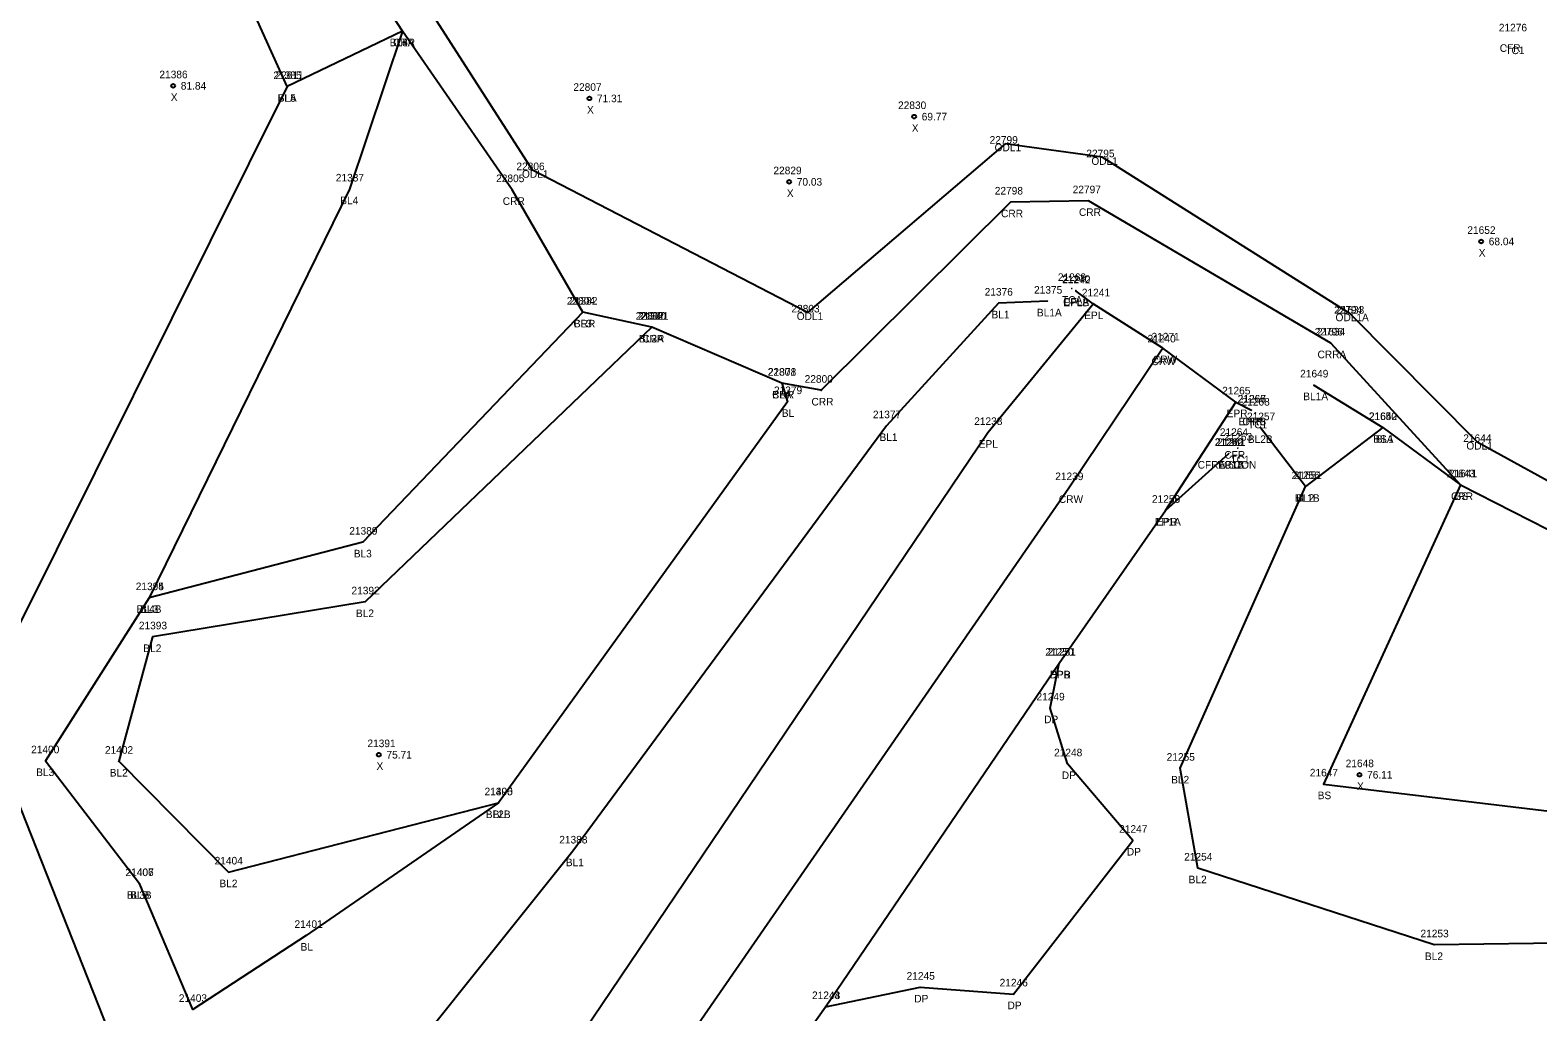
# Model space of a CAD drawing. Extents: x 2266664 to 2272385, y 716533 to 724777.
# Drawn here: x 2269825.5 to 2270024.3, y 721208.7 to 721338.1 of the extents above; entities that cross this region are included whole.
import ezdxf

# ---------------------------------------------------------------- set-up
doc = ezdxf.new("R2010")
doc.units = 0
for name, color, linetype in [('RD_DTM_BkLn1', 7, 'Continuous'), ('RD_DTM_BkLn2', 7, 'Continuous'), ('RD_EX_Conc_txCode', 7, 'Continuous'), ('RD_EX_Driveway', 7, 'Continuous'), ('RD_EX_Driveway_txCode', 7, 'Continuous'), ('RD_EX_H2O', 7, 'Continuous'), ('RD_EX_H2O_txCode', 7, 'Continuous'), ('RD_EX_Road', 7, 'Continuous'), ('RD_EX_Road_txCode', 7, 'Continuous'), ('RD_Sketch8', 7, 'Continuous'), ('RD_SMD_Locator', 7, 'Continuous'), ('RD_SMD_Misc', 7, 'Continuous')]:
    doc.layers.add(name, color=color, linetype=linetype)

msp = doc.modelspace()

# ---------------------------------------------------------------- linework, layer by layer
at = {"layer": 'RD_DTM_BkLn1'}
for points in [[(2269859.38, 721330.7), (2269841.69, 721369.98), (2269832.71, 721368.75)], [(2269874.61, 721338.02), (2269859.38, 721330.7), (2269818.8, 721249.22), (2269835.85, 721206.17)], [(2269874.61, 721338.02), (2269867.6, 721317.19), (2269841.23, 721263.3)], [(2269959.65, 721302.4), (2269953.17, 721302.14), (2269938.41, 721285.97), (2269897.06, 721229.9), (2269866, 721191.05), (2269835.85, 721206.17)], [(2269984.48, 721289.11), (2269974.85, 721296.23), (2269965.67, 721302.04)], [(2269907.47, 721298.96), (2269898.39, 721300.95), (2269869.39, 721270.62), (2269841.23, 721263.3), (2269827.53, 721241.79), (2269839.94, 721225.6)], [(2269907.47, 721298.96), (2269869.68, 721262.75), (2269841.64, 721258.14), (2269837.21, 721241.73), (2269851.67, 721227.13), (2269887.25, 721236.25)], [(2269213.98, 720188.15), (2269268.31, 720269.94), (2269268.47, 720270.09), (2269327.62, 720355.72), (2269383.6, 720437.51), (2269437.73, 720515.95), (2269495.99, 720600.52), (2269554.62, 720685.64), (2269615.22, 720774.38), (2269673.5, 720859.19), (2269731.5, 720942.79), (2269790.07, 721028.11), (2269844, 721106.36), (2269904.2, 721193.5), (2269962.45, 721277.81), (2269974.66, 721295.97), (2269974.85, 721296.23)], [(2269924.59, 721291.58), (2269925.37, 721289.15), (2269887.25, 721236.25), (2269861.92, 721218.77), (2269846.95, 721209.01), (2269839.94, 721225.6)], [(2269994.76, 721291.35), (2270003.84, 721285.73), (2269993.63, 721277.95)], [(2270089.16, 721218.61), (2270010.6, 721217.53), (2269979.45, 721227.65), (2269977.14, 721240.81), (2269993.63, 721277.95), (2269987.72, 721285.71)]]:
    msp.add_lwpolyline(points, dxfattribs=at)
at = {"layer": 'RD_DTM_BkLn2'}
msp.add_lwpolyline([(2270003.84, 721285.73), (2270014.08, 721278.19), (2269996.03, 721238.74), (2270067.72, 721230.16), (2270074.38, 721232.34)], dxfattribs=at)
at = {"layer": 'RD_EX_Driveway'}
msp.add_lwpolyline([(2269930.38, 721209.38), (2269942.85, 721211.94), (2269955.14, 721211.05), (2269970.87, 721231.31), (2269962.29, 721241.39), (2269959.97, 721248.76), (2269961.18, 721254.67)], dxfattribs=at)
at = {"layer": 'RD_EX_H2O'}
for points in [[(2269999.49, 721300.76), (2269966.83, 721321.38), (2269954.07, 721323.17), (2269927.99, 721300.92), (2269891.76, 721319.68), (2269857.29, 721373.38), (2269840.79, 721383.83), (2269835.63, 721388.54), (2269827.58, 721372.67), (2269808.71, 721364.34), (2269761.49, 721371.66), (2269756.17, 721368.61), (2269746.61, 721317.95), (2269761.51, 721302.75)], [(2269996.97, 721296.88), (2269965.03, 721315.64), (2269954.76, 721315.47), (2269929.78, 721290.65), (2269924.59, 721291.58), (2269907.47, 721298.96), (2269898.39, 721300.95), (2269889.07, 721317.1), (2269874.61, 721338.02), (2269854.27, 721369.2), (2269839.08, 721382.01), (2269832.71, 721368.75), (2269810.27, 721357.54), (2269761.21, 721366.63), (2269754.56, 721317.04), (2269765.82, 721305.79), (2269769.06, 721297.52)], [(2269999.49, 721300.76), (2270016.26, 721283.84), (2270043.79, 721268.73), (2270077.34, 721234.55), (2270090.18, 721221.74), (2270145.86, 721236.31), (2270165.48, 721256.74), (2270176.53, 721257.63), (2270190.3, 721240.29), (2270233.77, 721237.87), (2270299.69, 721290.51), (2270389.09, 721327.36), (2270474.84, 721354.23)], [(2269996.97, 721296.88), (2270014.08, 721278.19), (2270041.67, 721264.13), (2270074.38, 721232.34), (2270089.16, 721218.61), (2270140.31, 721226.6), (2270144.35, 721225.65), (2270163.36, 721234.25), (2270169.88, 721243.35), (2270177.39, 721245.92), (2270182.44, 721236.62), (2270238.2, 721231.39), (2270303.78, 721285.16), (2270310.34, 721288.45), (2270391.6, 721320.78), (2270477.31, 721344.54)]]:
    msp.add_lwpolyline(points, dxfattribs=at)
at = {"layer": 'RD_EX_Road'}
msp.add_line((2269975.2, 721274.82), (2269983.54, 721282.33), dxfattribs=at)
for points in [[(2269202.93, 720196.07), (2269237.22, 720244.72), (2269259.4, 720276.99), (2269259.41, 720277.21), (2269317.32, 720361.94), (2269369.05, 720437.36), (2269428.45, 720522.87), (2269487.41, 720608.15), (2269502.81, 720630.76), (2269544.96, 720692.14), (2269605.63, 720780.46), (2269663.95, 720865.82), (2269721.16, 720948.73), (2269780.45, 721034.57), (2269834.47, 721112.56), (2269853.48, 721140.68), (2269880.91, 721180.54), (2269894.87, 721200.75), (2269951.76, 721285.08), (2269965.67, 721302.04), (2269963.39, 721303.74)], [(2269222.47, 720182.37), (2269278.1, 720262.57), (2269277.83, 720263.03), (2269337.43, 720348.71), (2269393.72, 720430.44), (2269448.55, 720510.19), (2269506.62, 720593.92), (2269564.83, 720678.53), (2269625.78, 720767.57), (2269683.68, 720852.02), (2269741.8, 720936.18), (2269800.12, 721020.89), (2269854.32, 721099.54), (2269879.26, 721135.52), (2269912.84, 721184.64), (2269930.38, 721209.38), (2269961.18, 721254.67), (2269975.2, 721274.82), (2269984.48, 721289.11), (2269986.54, 721288.04)]]:
    msp.add_lwpolyline(points, dxfattribs=at)
at = {"layer": 'RD_SMD_Locator'}
for centre, radius in [((2269874.61, 721338.02), 0.001), ((2269874.61, 721338.02), 0.001), ((2269874.61, 721338.02), 0.001), ((2269844.38, 721330.8), 0.25), ((2269859.38, 721330.7), 0.001), ((2269859.38, 721330.7), 0.001), ((2269899.24, 721329.14), 0.25), ((2269942.05, 721326.74), 0.25), ((2269954.07, 721323.17), 0.001), ((2269966.83, 721321.38), 0.001), ((2269891.76, 721319.68), 0.001), ((2269867.6, 721317.19), 0.001), ((2269889.07, 721317.1), 0.001), ((2269925.58, 721318.14), 0.25), ((2269954.76, 721315.47), 0.001), ((2269965.03, 721315.64), 0.001), ((2270016.8, 721310.28), 0.25), ((2269962.82, 721304.07), 0.001), ((2269963.38, 721303.82), 0.001), ((2269963.39, 721303.74), 0.001), ((2269953.17, 721302.14), 0.001), ((2269959.65, 721302.4), 0.001), ((2269965.67, 721302.04), 0.001), ((2269898.39, 721300.95), 0.001), ((2269898.39, 721300.95), 0.001), ((2269927.99, 721300.92), 0.001), ((2269999.49, 721300.76), 0.001), ((2269999.49, 721300.76), 0.001), ((2269907.47, 721298.96), 0.001), ((2269907.47, 721298.96), 0.001), ((2269907.47, 721298.96), 0.001), ((2269974.66, 721295.97), 0.001), ((2269974.85, 721296.23), 0.001), ((2269996.97, 721296.88), 0.001), ((2269996.97, 721296.88), 0.001), ((2269924.59, 721291.58), 0.001), ((2269924.59, 721291.58), 0.001), ((2269994.76, 721291.35), 0.001), ((2269925.37, 721289.15), 0.001), ((2269929.78, 721290.65), 0.001), ((2269984.48, 721289.11), 0.001), ((2269986.54, 721288.04), 0.001), ((2269986.54, 721288.04), 0.001), ((2269987.03, 721287.64), 0.001), ((2269938.41, 721285.97), 0.001), ((2269987.72, 721285.71), 0.001), ((2270003.84, 721285.73), 0.001), ((2270003.84, 721285.73), 0.001), ((2269951.76, 721285.08), 0.001), ((2269984.17, 721283.64), 0.001), ((2270016.26, 721283.84), 0.001), ((2269983.54, 721282.33), 0.001), ((2269983.54, 721282.33), 0.001), ((2269983.54, 721282.33), 0.001), ((2269984.72, 721283.02), 0.001), ((2269962.45, 721277.81), 0.001), ((2269993.63, 721277.95), 0.001), ((2269993.63, 721277.95), 0.001), ((2270014.08, 721278.19), 0.001), ((2270014.08, 721278.19), 0.001), ((2269975.2, 721274.82), 0.001), ((2269975.2, 721274.82), 0.001), ((2269869.39, 721270.62), 0.001), ((2269841.23, 721263.3), 0.001), ((2269841.23, 721263.3), 0.001), ((2269869.68, 721262.75), 0.001), ((2269841.64, 721258.14), 0.001), ((2269961.18, 721254.67), 0.001), ((2269961.18, 721254.67), 0.001), ((2269959.97, 721248.76), 0.001), ((2269827.53, 721241.79), 0.001), ((2269837.21, 721241.73), 0.001), ((2269871.49, 721242.6), 0.25), ((2269962.29, 721241.39), 0.001), ((2269977.14, 721240.81), 0.001), ((2270000.76, 721239.96), 0.25), ((2269996.03, 721238.74), 0.001), ((2269887.25, 721236.25), 0.001), ((2269887.25, 721236.25), 0.001), ((2269897.06, 721229.9), 0.001), ((2269970.87, 721231.31), 0.001), ((2269979.45, 721227.65), 0.001), ((2269839.94, 721225.6), 0.001), ((2269839.94, 721225.6), 0.001), ((2269851.67, 721227.13), 0.001), ((2269861.92, 721218.77), 0.001), ((2270010.6, 721217.53), 0.001), ((2269942.85, 721211.94), 0.001), ((2269955.14, 721211.05), 0.001), ((2269846.95, 721209.01), 0.001), ((2269930.38, 721209.38), 0.001), ((2269930.38, 721209.38), 0.001)]:
    msp.add_circle(centre, radius, dxfattribs=at)

# ---------------------------------------------------------------- texts
at = {"layer": 'RD_EX_Conc_txCode'}
for s, p in [('CFR', (2270019.25, 721335.28)), ('21270', (2269961.55, 721304.82)), ('CFLA', (2269961.69, 721301.82)), ('21267', (2269984.72, 721289.04)), ('21264', (2269982.35, 721284.64)), ('CFR', (2269985.31, 721286.04)), ('21261', (2269982, 721283.33)), ('CFRA 6CON', (2269979.43, 721280.33)), ('CFR', (2269982.94, 721281.64))]:
    msp.add_text(s, height=1, dxfattribs=at).set_placement(p)
at = {"layer": 'RD_EX_Driveway_txCode'}
for s, p in [('21250', (2269959.34, 721255.67)), ('DPB', (2269959.92, 721252.67)), ('21249', (2269958.18, 721249.76)), ('DP', (2269959.19, 721246.76)), ('21248', (2269960.5, 721242.39)), ('DP', (2269961.51, 721239.39)), ('21247', (2269969.08, 721232.31)), ('DP', (2269970.09, 721229.31)), ('21245', (2269941.06, 721212.94)), ('21246', (2269953.32, 721212.05)), ('21244', (2269928.59, 721210.38)), ('DP', (2269942.07, 721209.94)), ('DP', (2269954.36, 721209.05))]:
    msp.add_text(s, height=1, dxfattribs=at).set_placement(p)
at = {"layer": 'RD_EX_H2O_txCode'}
for s, p in [('CRR', (2269873.36, 721336.02)), ('22799', (2269952, 721323.17)), ('ODL1', (2269952.66, 721322.17)), ('22795', (2269964.75, 721321.38)), ('ODL1', (2269965.42, 721320.38)), ('22805', (2269886.95, 721318.1)), ('22806', (2269889.62, 721319.68)), ('ODL1', (2269890.36, 721318.68)), ('22798', (2269952.68, 721316.47)), ('22797', (2269962.95, 721316.64)), ('CRR', (2269887.82, 721315.1)), ('CRR', (2269953.51, 721313.47)), ('CRR', (2269963.78, 721313.64)), ('22804', (2269896.27, 721301.95)), ('22803', (2269925.87, 721300.92)), ('22794', (2269997.41, 721300.76)), ('21633', (2269997.67, 721300.76)), ('CRR', (2269897.13, 721298.95)), ('22802', (2269905.35, 721299.96)), ('ODL1', (2269926.58, 721299.92)), ('ODL1A', (2269997.6, 721299.76)), ('ODL1A', (2269997.6, 721299.76)), ('CRR', (2269906.22, 721296.96)), ('22796', (2269994.86, 721297.88)), ('21634', (2269995.15, 721297.88)), ('CRRA', (2269995.23, 721294.88)), ('CRRA', (2269995.23, 721294.88)), ('22801', (2269922.75, 721292.58)), ('22800', (2269927.62, 721291.65)), ('CRR', (2269923.34, 721289.58)), ('CRR', (2269928.52, 721288.65)), ('21644', (2270014.44, 721283.84)), ('ODL1', (2270014.85, 721282.84)), ('21641', (2270012.54, 721279.19)), ('CRR', (2270012.83, 721276.19))]:
    msp.add_text(s, height=1, dxfattribs=at).set_placement(p)
at = {"layer": 'RD_EX_Road_txCode'}
for s, p in [('21242', (2269961.59, 721304.74)), ('21241', (2269964.16, 721303.04)), ('EPLB', (2269961.71, 721301.74)), ('EPL', (2269964.47, 721300.04)), ('21265', (2269982.66, 721290.11)), ('21266', (2269984.69, 721289.04)), ('EPR', (2269983.25, 721287.11)), ('21238', (2269949.97, 721286.08)), ('EPRB', (2269984.83, 721286.04)), ('EPL', (2269950.56, 721283.08)), ('21260', (2269981.68, 721283.33)), ('EP1B', (2269982.14, 721280.33)), ('21258', (2269973.4, 721275.82)), ('21259', (2269973.4, 721275.82)), ('EP1A', (2269973.79, 721272.82)), ('EPR', (2269973.97, 721272.82)), ('21251', (2269959.66, 721255.67)), ('EPR', (2269959.95, 721252.67)), ('21243', (2269928.59, 721210.38))]:
    msp.add_text(s, height=1, dxfattribs=at).set_placement(p)
at = {"layer": 'RD_Sketch8'}
for s, p in [('21386', (2269842.56, 721331.8)), ('81.84', (2269845.38, 721330.3)), ('22807', (2269897.13, 721330.14)), ('X', (2269844.06, 721328.8)), ('71.31', (2269900.24, 721328.64)), ('X', (2269898.93, 721327.14)), ('22830', (2269939.93, 721327.74)), ('69.77', (2269943.05, 721326.24)), ('X', (2269941.74, 721324.74)), ('22829', (2269923.5, 721319.14)), ('X', (2269925.27, 721316.14)), ('70.03', (2269926.58, 721317.64)), ('21652', (2270014.98, 721311.28)), ('X', (2270016.48, 721308.28)), ('68.04', (2270017.8, 721309.78)), ('21391', (2269869.98, 721243.6)), ('X', (2269871.18, 721240.6)), ('75.71', (2269872.49, 721242.1)), ('21648', (2269998.94, 721240.96)), ('76.11', (2270001.76, 721239.46)), ('X', (2270000.44, 721237.96))]:
    msp.add_text(s, height=1, dxfattribs=at).set_placement(p)
at = {"layer": 'RD_SMD_Misc'}
for s, p in [('21276', (2270019.13, 721337.98)), ('BL4A', (2269872.92, 721336.02)), ('BL5A', (2269872.92, 721336.02)), ('TC1', (2270019.99, 721334.98)), ('21385', (2269857.58, 721331.7)), ('22811', (2269857.86, 721331.7)), ('BLA', (2269858.13, 721328.7)), ('BL5', (2269858.17, 721328.7)), ('21387', (2269865.81, 721318.19)), ('BL4', (2269866.4, 721315.19)), ('21269', (2269961, 721305.07)), ('21376', (2269951.35, 721303.14)), ('21375', (2269957.86, 721303.4)), ('TCA', (2269961.54, 721302.07)), ('21382', (2269896.59, 721301.95)), ('BL1', (2269952.25, 721300.14)), ('BL1A', (2269958.24, 721300.4)), ('BL3', (2269897.18, 721298.95)), ('21380', (2269905.64, 721299.96)), ('21381', (2269905.96, 721299.96)), ('BL2A', (2269905.78, 721296.96)), ('BL3A', (2269905.78, 721296.96)), ('21240', (2269972.82, 721296.97)), ('21271', (2269973.34, 721297.23)), ('CRW', (2269973.53, 721294.23)), ('21378', (2269922.79, 721292.58)), ('CRW', (2269973.34, 721293.97)), ('21649', (2269992.94, 721292.35)), ('21379', (2269923.57, 721290.15)), ('BLA', (2269923.35, 721289.58)), ('21268', (2269985.21, 721288.64)), ('BL1A', (2269993.35, 721289.35)), ('BL', (2269924.61, 721287.15)), ('21377', (2269936.62, 721286.97)), ('21257', (2269985.93, 721286.71)), ('21650', (2270001.98, 721286.73)), ('21642', (2270002.02, 721286.73)), ('TC1', (2269986.07, 721285.64)), ('BL1', (2269937.49, 721283.97)), ('21262', (2269981.72, 721283.33)), ('21263', (2269982.9, 721284.02)), ('BL2B', (2269986.04, 721283.71)), ('BSA', (2270002.57, 721283.73)), ('BL1', (2270002.92, 721283.73)), ('TC1A', (2269982.09, 721280.33)), ('TC1', (2269983.75, 721281.02)), ('21239', (2269960.65, 721278.81)), ('21256', (2269991.81, 721278.95)), ('21651', (2269992.09, 721278.95)), ('21643', (2270012.26, 721279.19)), ('BS', (2270013.3, 721276.19)), ('CRW', (2269961.13, 721275.81)), ('BL1B', (2269992.23, 721275.95)), ('BL2', (2269992.42, 721275.95)), ('21389', (2269867.59, 721271.62)), ('BL3', (2269868.18, 721268.62)), ('21394', (2269839.44, 721264.3)), ('21395', (2269839.44, 721264.3)), ('21392', (2269867.88, 721263.75)), ('BL4B', (2269839.56, 721261.3)), ('BL3', (2269840.03, 721261.3)), ('BL2', (2269868.47, 721260.75)), ('21393', (2269839.85, 721259.14)), ('BL2', (2269840.44, 721256.14)), ('21400', (2269825.65, 721242.79)), ('21402', (2269835.38, 721242.73)), ('21255', (2269975.34, 721241.81)), ('BL3', (2269826.32, 721239.79)), ('BL2', (2269836.01, 721239.73)), ('BL2', (2269975.93, 721238.81)), ('21647', (2269994.21, 721239.74)), ('21390', (2269885.42, 721237.25)), ('21405', (2269885.42, 721237.25)), ('BS', (2269995.25, 721236.74)), ('BL2B', (2269885.58, 721234.25)), ('BL', (2269886.5, 721234.25)), ('21388', (2269895.27, 721230.9)), ('21254', (2269977.65, 721228.65)), ('21406', (2269838.08, 721226.6)), ('21407', (2269838.1, 721226.6)), ('21404', (2269849.84, 721228.13)), ('BL1', (2269896.14, 721227.9)), ('BL2', (2269850.47, 721225.13)), ('BL2', (2269978.24, 721225.65)), ('BL3B', (2269838.26, 721223.6)), ('BLB', (2269838.71, 721223.6)), ('21401', (2269860.37, 721219.77)), ('BL', (2269861.17, 721216.77)), ('21253', (2270008.8, 721218.53)), ('BL2', (2270009.39, 721215.53)), ('21403', (2269845.12, 721210.01))]:
    msp.add_text(s, height=1, dxfattribs=at).set_placement(p)

doc.saveas('drawing.dxf')
